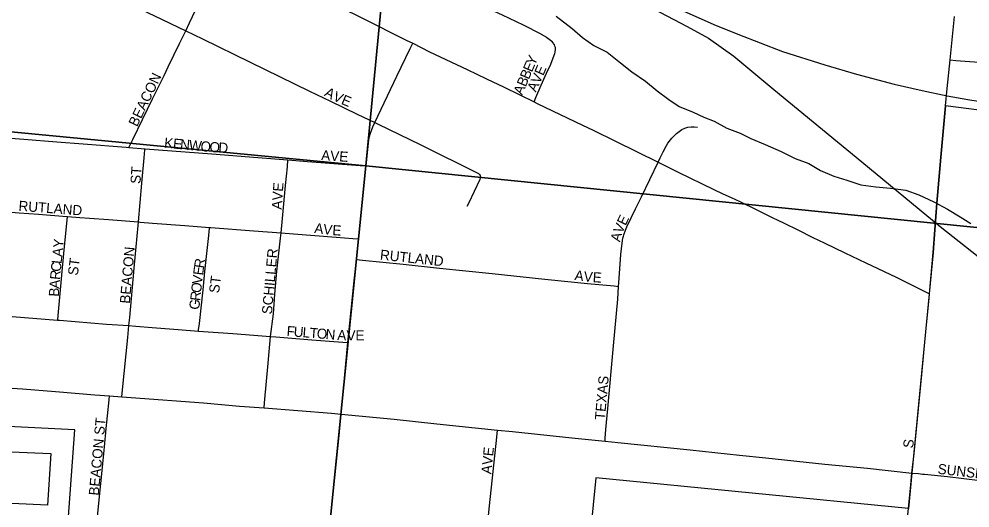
# Model space of a CAD drawing. Extents: x 1410790 to 1770854, y 566777 to 831614.
# Drawn here: x 1607334 to 1612046, y 695774 to 698196 of the extents above; entities that cross this region are included whole.
import ezdxf

# ---------------------------------------------------------------- set-up
doc = ezdxf.new("R2010")
doc.units = 0
for name, color, linetype in [('GM_X_City_Street', 7, 'Continuous'), ('GM_X_City_Street_Text', 7, 'Continuous'), ('GM_X_Corporation', 7, 'Continuous'), ('GM_X_Minor_River', 7, 'Continuous'), ('GM_X_Rail_Line', 7, 'Continuous'), ('GM_X_Section', 7, 'Continuous'), ('GM_X_Township_Road', 7, 'Continuous'), ('GM_X_Township_Subdivision', 7, 'Continuous'), ('GM_X_Township_Subdivision_Text', 7, 'Continuous')]:
    doc.layers.add(name, color=color, linetype=linetype)

msp = doc.modelspace()

# ---------------------------------------------------------------- linework, layer by layer
at = {"layer": 'GM_X_City_Street'}
for points in [[(1607265.8, 698570.1), (1607341.1, 698534.1), (1607415.1, 698498.5), (1607503.7, 698455.4), (1607563, 698427), (1607666.1, 698376.6), (1607813.6, 698304.9), (1608005.3, 698212.2), (1608159.5, 698138.1)], [(1608159.5, 698138.1), (1608178.2, 698177.2), (1608283.2, 698397.7), (1608334.1, 698501.2), (1608349.4, 698532.4)], [(1609040.3, 698528.7), (1609056.9, 698519.8), (1609115.5, 698490.7), (1609219.8, 698443.2), (1609429.6, 698350.3), (1609624.3, 698264.6), (1609728.3, 698216.6), (1609831.8, 698167.3), (1609919.3, 698122.5), (1609921.9, 698121), (1609947.4, 698106.1), (1609954.1, 698101.7), (1609960.7, 698096.6), (1609967.2, 698091.6), (1609973.4, 698085.7)], [(1608916.3, 698258.6), (1608928.4, 698252.8), (1609031.8, 698202.8), (1609251.8, 698092.1), (1609284.6, 698075.7)], [(1611947.4, 697993.7), (1611969.1, 698208.1)], [(1607878.1, 697559.5), (1607881.2, 697565.7), (1607897.7, 697598.6), (1607945.6, 697698.6), (1607994.5, 697800.6), (1608052.6, 697916.5), (1608073, 697959.6), (1608128.9, 698075.1), (1608159.5, 698138.1)], [(1608159.5, 698138.1), (1608242.3, 698098.3), (1608478.8, 697982.9), (1608773.1, 697839.2), (1608877.3, 697788.5), (1609008.6, 697725.4), (1609096.6, 697683.3)], [(1609096.6, 697683.3), (1609205.7, 697912.4), (1609271.8, 698049.4), (1609284.6, 698075.7)], [(1609284.6, 698075.7), (1609368.1, 698034.4), (1609554.1, 697946.2), (1609650.8, 697900.6), (1609737, 697858), (1609885.7, 697785.3)], [(1609885.7, 697785.3), (1609894.9, 697806.7), (1609921.4, 697868.3), (1609948.3, 697927.1), (1609968.5, 697972.5), (1609985.6, 698017.3), (1609988.2, 698026.1), (1609990.2, 698032.7), (1609991.2, 698038.4), (1609991.4, 698041.2), (1609991.7, 698044.1), (1609991.7, 698047.9), (1609991.4, 698054.5), (1609989.5, 698061.8), (1609986.7, 698068.7), (1609982.9, 698074.7), (1609980.3, 698078.7), (1609973.4, 698085.7)], [(1611846.1, 696834.4), (1611863.9, 697039.6), (1611871.7, 697152.1), (1611881.6, 697283.4), (1611901.4, 697511.5), (1611924.8, 697765.7), (1611933.1, 697852.1), (1611947.4, 697993.7)], [(1611947.4, 697993.7), (1611975.5, 697991.3), (1612067.8, 697983.4), (1612243.8, 697965.9)], [(1609885.7, 697785.3), (1609900.9, 697777.8), (1610125.9, 697669.6), (1610178.1, 697645.5), (1610396.1, 697537.7), (1610500.2, 697486.6)], [(1609053.3, 697468.3), (1609061.4, 697549.4), (1609067.2, 697598.3), (1609070.3, 697613.9), (1609075, 697631.1), (1609086.4, 697661.9), (1609096.6, 697683.3)], [(1609096.6, 697683.3), (1609114.1, 697674.7), (1609321.2, 697574.7), (1609610.8, 697430.8), (1609612.5, 697429.7), (1609613.6, 697428.9), (1609616.3, 697426.6), (1609619.7, 697421.6)], [(1610500.2, 697486.6), (1610511.1, 697508.9), (1610525.2, 697538), (1610540, 697566.9), (1610548.7, 697580.5), (1610568.8, 697606.1), (1610579.9, 697618), (1610591.8, 697629.1), (1610604.5, 697639.2), (1610618, 697648.1), (1610632.5, 697655.4), (1610647.9, 697660.5), (1610664, 697662.5), (1610680.1, 697661.7), (1610696.2, 697659.8)], [(1607252.6, 697608.8), (1607357.5, 697600.8), (1607521, 697588.2), (1607651.7, 697577.6), (1607864.1, 697560.6), (1607878.1, 697559.5)], [(1607878.1, 697559.5), (1607958.4, 697553.3)], [(1607925.7, 697191.1), (1607942.8, 697383.2), (1607954.3, 697508), (1607957.9, 697547.8), (1607958.4, 697553.3)], [(1607958.4, 697553.3), (1608289, 697527.7), (1608517.9, 697510.9), (1608666.4, 697498.7)], [(1608632.3, 697136.5), (1608638.8, 697208.8), (1608654, 697372.3), (1608663.5, 697463.9), (1608666.4, 697498.7)], [(1608666.4, 697498.7), (1608762.8, 697490.8), (1609024, 697470.7), (1609053.3, 697468.3)], [(1609017.3, 697107.5), (1609022.9, 697158.7), (1609045.3, 697387.4), (1609053.3, 697468.3)], [(1610305.2, 696871.6), (1610306.6, 696889.7), (1610316.5, 697029.9), (1610322.2, 697085.6), (1610326.3, 697110.5), (1610328.4, 697120), (1610330.4, 697127.1), (1610338.8, 697150.2), (1610346.2, 697166.8), (1610389.4, 697256.4), (1610418, 697315.3), (1610500.2, 697486.6)], [(1610500.2, 697486.6), (1610600.1, 697437.5), (1610776.5, 697351.3), (1610821.1, 697330.8), (1610862.7, 697312.2), (1610906.3, 697292.1), (1610993.5, 697249.1), (1611065.7, 697213.5), (1611094.3, 697200), (1611124.9, 697184.9), (1611193, 697151.8), (1611268.2, 697114.7), (1611324.3, 697087.7), (1611426.1, 697038.5), (1611530.8, 696988.4), (1611680.7, 696916.7), (1611805.5, 696854.6), (1611846.1, 696834.4)], [(1609555.2, 697269.9), (1609562.4, 697283.6), (1609618.9, 697403.2), (1609619.7, 697405.1), (1609620.3, 697407), (1609621, 697409.5), (1609621.6, 697413.8), (1609619.7, 697421.6)], [(1607218.2, 697245.2), (1607221.1, 697245), (1607234.1, 697244.2), (1607334.7, 697236.8), (1607429.4, 697229.2), (1607571.2, 697217.6), (1607574.1, 697217.4)], [(1607524.9, 696704.5), (1607525.2, 696707.4), (1607528.8, 696745), (1607542.8, 696890.2), (1607557.8, 697052.7), (1607570.8, 697182.5), (1607574.1, 697217.4)], [(1607574.1, 697217.4), (1607635.1, 697212.9), (1607682.8, 697209.4), (1607777.9, 697202.7), (1607925.7, 697191.1)], [(1607878.1, 696677.5), (1607882, 696716.9), (1607904.1, 696961.3), (1607924.1, 697172.6), (1607925.7, 697191.1)], [(1607925.7, 697191.1), (1607933.2, 697190.5), (1607995, 697185.5), (1608155, 697172.9), (1608277.7, 697163.6)], [(1608223.3, 696650.6), (1608223.9, 696656.1), (1608227.4, 696688.2), (1608245.8, 696855.4), (1608255.3, 696945.9), (1608274, 697124.4), (1608277.4, 697160.3), (1608277.7, 697163.6)], [(1608277.7, 697163.6), (1608285, 697163.1), (1608497.6, 697147), (1608632.3, 697136.5)], [(1608580.2, 696623.2), (1608594.7, 696735.6), (1608602, 696833.5), (1608611.8, 696947.9), (1608630, 697110.8), (1608632.3, 697136.5)], [(1608632.3, 697136.5), (1608693.5, 697131.7), (1608905.7, 697115.3), (1608987.4, 697109.6), (1609017.3, 697107.5)], [(1609006.2, 697004.9), (1609017.3, 697107.5)], [(1608963.2, 696594), (1608966.1, 696624.9), (1608994.8, 696899.4), (1609006.2, 697004.9)], [(1609006.2, 697004.9), (1609036.3, 697001.8), (1609236.7, 696981.1), (1609416.9, 696962.4), (1609547.4, 696948.4), (1609677.9, 696935), (1609939, 696908.2), (1610151.5, 696886.8), (1610282.2, 696873.9), (1610305.2, 696871.6)], [(1610237.7, 696105.2), (1610238.8, 696120), (1610242.3, 696163.7), (1610251.3, 696267.4), (1610279, 696577.2), (1610300.3, 696808), (1610305.2, 696871.6)], [(1611758.5, 695947.3), (1611769.6, 696044.3), (1611807.6, 696435.5), (1611824.9, 696613.5), (1611844.1, 696811.5), (1611846.1, 696834.4)], [(1607170.2, 696732.4), (1607206.4, 696729), (1607299.6, 696722.4), (1607524.9, 696704.5)], [(1607524.9, 696704.5), (1607534, 696703.8), (1607767.5, 696685.3), (1607878.1, 696677.5)], [(1607843.6, 696325.1), (1607846.8, 696358.7), (1607854.5, 696440.3), (1607864.3, 696537.8), (1607872.3, 696619.3), (1607878.1, 696677.5)], [(1607878.1, 696677.5), (1607912.8, 696675), (1607993.6, 696668.6), (1608122.3, 696658.3), (1608223.3, 696650.6)], [(1608223.3, 696650.6), (1608393.4, 696637.6), (1608580.2, 696623.2)], [(1608548.6, 696269.4), (1608550.8, 696295.6), (1608567.5, 696490.9), (1608580.2, 696623.2)], [(1608580.2, 696623.2), (1608605.5, 696621.4), (1608784.8, 696607.1), (1608938.6, 696595.8), (1608963.2, 696594)], [(1608930.1, 696238.9), (1608930.7, 696245.2), (1608933.6, 696275.4), (1608941.6, 696363.9), (1608963.2, 696594)], [(1607137.1, 696378.1), (1607219.9, 696372.2), (1607350.5, 696363.9), (1607513.7, 696350.5), (1607709.7, 696335.3), (1607782.1, 696329.8)], [(1607681.7, 695396.6), (1607684.5, 695423.1), (1607691.1, 695483.2), (1607700.5, 695581.1), (1607701.6, 695590.7), (1607708.6, 695647.1), (1607708.8, 695648.5), (1607709.1, 695649.7), (1607714.5, 695672.3), (1607718.4, 695695.1), (1607718.7, 695696.7), (1607718.9, 695698.8), (1607738.5, 695894.6), (1607753.6, 696042.6), (1607764.1, 696148.8), (1607764.4, 696151.1), (1607780.2, 696309.8), (1607782.1, 696329.8)], [(1607782.1, 696329.8), (1607843.6, 696325.1)], [(1607843.6, 696325.1), (1607889, 696321.6), (1608247.9, 696294.6), (1608426.4, 696278.9), (1608548.6, 696269.4)], [(1608548.6, 696269.4), (1608882.7, 696243.3), (1608930.1, 696238.9)], [(1608821.9, 695131.7), (1608825.6, 695168.9), (1608839.2, 695298.8), (1608849, 695392.1), (1608864.4, 695568.9), (1608872.1, 695650), (1608879.4, 695730.3), (1608883.6, 695778.8), (1608889.7, 695843.3), (1608919.5, 696133.7), (1608930.1, 696238.9)], [(1608930.1, 696238.9), (1609192.6, 696213.4), (1609404.5, 696191.5), (1609704.8, 696160.1)], [(1609605.5, 695238.1), (1609610.6, 695284.4), (1609637, 695526.7), (1609649.6, 695639.7), (1609665.7, 695785), (1609701.1, 696124.3), (1609704.8, 696160.1)], [(1609704.8, 696160.1), (1609779.4, 696152.3), (1610072.7, 696122), (1610237.7, 696105.2)], [(1610237.7, 696105.2), (1610300.9, 696098.7), (1610659.4, 696061.9), (1610903.8, 696036.1), (1611034, 696022.2), (1611327.4, 695991.9), (1611538.6, 695971), (1611758.5, 695947.3)], [(1611753, 695889.3), (1611758.5, 695947.3)], [(1611758.5, 695947.3), (1611790.6, 695944.4), (1611811, 695942.3)]]:
    msp.add_lwpolyline(points, dxfattribs=at)
at = {"layer": 'GM_X_Corporation'}
msp.add_lwpolyline([(1613263.8, 694806.5), (1613694.3, 697538.3), (1611924.8, 697765.7), (1611901.4, 697511.5), (1611881.6, 697283.4), (1611871.7, 697152.1), (1611863.9, 697039.6), (1611758.5, 695947.3), (1611742, 695771.4), (1610192.7, 695923.9), (1610136.8, 695371.8)], dxfattribs=at)
msp.add_lwpolyline([(1606218.3, 696231.3), (1606233.3, 696096.4), (1607490.6, 696043.7), (1607474, 695787.9), (1606587.2, 695829.6), (1606577.2, 695914.6), (1606252.3, 695926), (1606297.6, 695518.4), (1606375.8, 695507.4), (1606667.6, 695497.2), (1606689.5, 695494.9), (1606729.5, 695668.3), (1606974.2, 695655.5), (1607570.9, 695617.4), (1607610.9, 696161.2)], close=True, dxfattribs=at)
at = {"layer": 'GM_X_Minor_River'}
msp.add_lwpolyline([(1609995.2, 698210.1), (1610074.7, 698149.4), (1610126.3, 698105), (1610181.9, 698064.5), (1610247.5, 698032), (1610315.1, 697979.5), (1610370.6, 697935), (1610438.2, 697888.5), (1610495.8, 697840), (1610553.4, 697797.5), (1610605, 697763.1), (1610674.7, 697734.5), (1610726.5, 697710.1), (1610778.3, 697689.7), (1610841.9, 697655.2), (1610907.6, 697630.7), (1610959.4, 697604.3), (1611031, 697573.8), (1611110.7, 697539.1), (1611180.3, 697504.6), (1611248.1, 697480), (1611305.7, 697445.6), (1611371.4, 697417.1), (1611435.2, 697398.6), (1611504.9, 697374), (1611578.8, 697365.5), (1611652.6, 697358.9), (1611728.4, 697348.4), (1611792.2, 697325.9), (1611867.8, 697291.3), (1611935.4, 697254.8), (1611997.1, 697216.2), (1612050.8, 697183.8)], dxfattribs=at)
at = {"layer": 'GM_X_Rail_Line'}
for points in [[(1604421.4, 701434.4), (1604462.9, 701401.9), (1610644.1, 698159.2), (1610749.6, 698101.7), (1610875.2, 698011.5), (1611073.6, 697847.6), (1611509.9, 697489), (1611898.2, 697167.8), (1612565.6, 696641.4)], [(1610394.3, 698347.2), (1610565.5, 698262.7), (1610776.4, 698169.7), (1610896.2, 698120.4), (1611117.5, 698036), (1611326.8, 697968.7), (1611483, 697922.6), (1611670.5, 697873.5), (1611809, 697842.4), (1611933, 697815.8), (1612034.8, 697797.2), (1612239.9, 697764.2), (1612374.7, 697746.4), (1612557.8, 697727.3), (1612813.6, 697700.4), (1613128.8, 697667.1), (1613271.6, 697651.8), (1613443.4, 697633.5), (1613660.2, 697611.3)]]:
    msp.add_lwpolyline(points, dxfattribs=at)
at = {"layer": 'GM_X_Section'}
for points in [[(1604192.4, 703233.9), (1609553.2, 702682.3), (1609051.7, 697468.6), (1603688.3, 697982.3)], [(1609553.2, 702682.3), (1615120.2, 702135.6), (1614682.3, 696901), (1609051.7, 697468.6)], [(1609051.7, 697468.6), (1608507.1, 692045.6), (1603189.9, 692572.7), (1603688.3, 697982.3)], [(1609051.7, 697468.6), (1614682.3, 696901), (1614129.7, 691476), (1608507.1, 692045.6)]]:
    msp.add_lwpolyline(points, close=True, dxfattribs=at)
at = {"layer": 'GM_X_Township_Road'}
msp.add_lwpolyline([(1611668.9, 695136.7), (1611680.2, 695221.5), (1611704.2, 695417.3), (1611742, 695771.4), (1611753, 695889.3)], dxfattribs=at)
at = {"layer": 'GM_X_Township_Subdivision'}
msp.add_lwpolyline([(1611811, 695942.3), (1611820.4, 695941.3), (1611934.4, 695929.4), (1612178, 695900.3), (1612340.9, 695884.6), (1612487.1, 695869), (1612600.7, 695855.3), (1612714.6, 695842.4), (1612990.1, 695813.3), (1613085.4, 695803.3)], dxfattribs=at)

# ---------------------------------------------------------------- texts
at = {"layer": 'GM_X_City_Street_Text'}
for s, rotation, p in [('Y', 65.5759, (1609888.9, 697961.9)), ('E', 67.0113, (1609875.3, 697929.8)), ('E', 66.8167, (1609931.4, 697912.6)), ('BEACON', 64.3252, (1607918.8, 697659.2)), ('B', 67.015, (1609859.8, 697893.4)), ('V', 65.723, (1609912.9, 697871.5)), ('B', 67.0214, (1609844.4, 697856.9)), ('A', 65.5759, (1609894.6, 697831.3)), ('A', 331.988, (1608842.9, 697817.3)), ('V', 336.3291, (1608885.5, 697794.8)), ('A', 67.0296, (1609827.2, 697816.4)), ('E', 337.1667, (1608926.5, 697776.8)), ('K', 354.7244, (1608051.4, 697558.9)), ('E', 354.719, (1608095.2, 697554.9)), ('N', 354.7244, (1608130.2, 697551.6)), ('W', 354.7211, (1608174, 697547.6)), ('O', 354.778, (1608231.1, 697542.3)), ('O', 356.0857, (1608276.1, 697538.2)), ('D', 356.801, (1608320.7, 697535.2)), ('AVE', 356.0531, (1608830, 697497.3)), ('ST', 86.4258, (1607935.5, 697378.5)), ('AVE', 85.9088, (1608635.1, 697251)), ('RUTLAND', 355.6694, (1607329.9, 697246.5)), ('E', 64.6447, (1610339.5, 697169.7)), ('A', 353.3738, (1608795.3, 697136.5)), ('V', 353.3844, (1608839, 697131.4)), ('E', 355.848, (1608885, 697126.1)), ('V', 66.6479, (1610322.2, 697129.8)), ('A', 75.1685, (1610311.6, 697089.1)), ('Y', 84.2823, (1607552.1, 697060.3)), ('A', 84.2763, (1607547.8, 697016.5)), ('BEACON', 84.9895, (1607882.7, 696784.8)), ('SCHILLER', 84.8807, (1608586.7, 696731.8)), ('RUTLAND', 353.9451, (1609120.8, 697004.5)), ('C', 84.2834, (1607540.3, 696942.1)), ('L', 84.2799, (1607544.3, 696981.5)), ('ST', 82.8657, (1607624.9, 696924)), ('R', 81.468, (1608249.9, 696959.2)), ('R', 84.4537, (1607536.5, 696902.7)), ('V', 83.4975, (1608240.4, 696881)), ('E', 82.631, (1608245.4, 696924.5)), ('A', 352.5036, (1610084.6, 696903.3)), ('V', 354.3893, (1610130, 696897.4)), ('E', 356.1136, (1610175.4, 696892.9)), ('A', 85.7337, (1607533.2, 696859.1)), ('O', 83.4975, (1608235.4, 696837.3)), ('ST', 82.8649, (1608324.5, 696836)), ('B', 86.3547, (1607530.7, 696819.7)), ('R', 83.5003, (1608231, 696797.9)), ('G', 83.4945, (1608226, 696754.2)), ('F', 355.5562, (1608658.5, 696626.2)), ('U', 355.5448, (1608693.5, 696623.4)), ('L', 355.5578, (1608737.4, 696620)), ('T', 355.5562, (1608772.5, 696617.3)), ('O', 355.5448, (1608807.6, 696614.6)), ('N', 355.5594, (1608851.5, 696611.1)), ('A', 357.0991, (1608910, 696606.6)), ('V', 359.8295, (1608956.6, 696604.3)), ('E', 359.9956, (1609000.7, 696604.2)), ('TEXAS', 84.9232, (1610236.7, 696208.4)), ('BEACON ST', 84.807, (1607728.7, 695834.2)), ('S', 82.8783, (1611763.6, 696067.9)), ('AVE', 84.0899, (1609673.5, 695940.1))]:
    msp.add_text(s, height=50, rotation=rotation, dxfattribs=at).set_placement(p)
at = {"layer": 'GM_X_Township_Subdivision_Text'}
msp.add_text('SUNSET', height=50, rotation=353.4177, dxfattribs=at).set_placement((1611884, 695944.1))

doc.saveas('drawing.dxf')
